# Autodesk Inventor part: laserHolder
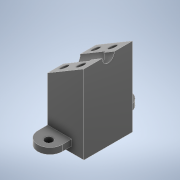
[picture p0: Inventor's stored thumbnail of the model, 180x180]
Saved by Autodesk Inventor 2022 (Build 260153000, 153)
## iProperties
Created: 2022-11
Part Number: laserHolder
Material: Acetal Resin, Black
Document SubType Name: Modeling
Designer: Wojtus
Density: 1.425 g/cm^3
Appearance: Smooth - Black
Author: Wojtus
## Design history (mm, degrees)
sketch "Sketch1"
  geometry: L1 (7.5, -10)-(7.5, 10); L2 (7.5, 10)-(-7.5, 10); L3 (-7.5, 10)-(-7.5, -10); L4 (-7.5, -10)-(7.5, 10); L5 (7.5, -10)-(-7.5, 10); L6 (7.5, -10)-(-7.5, -10); L7 (7.5, 10)-(-2.5, 10); L8 (-2.5, 10)-(-2.5, 14); L9 (7.5, 14)-(7.5, 10); L10 (-7.5, -10)-(-5.5, -10); L11 (0.5, -10)-(7.5, -10); L12 (0, 0)-(-3.6, 0); L13 (7.5, -14)-(7.5, -10); L14 (-2.5, -10)-(-2.5, -14); A1 r 5 centre (2.5, 14) between (7.5, 14) and (-2.5, 14); A2 r 5 centre (2.5, -14) between (-2.5, -14) and (7.5, -14); 8 further points
  constraints: 28 end point, 5 horizontal, 4 parallel, 4 point on circle, 4 symmetric about line, 3 perpendicular, 3 point on line, 2 centre point, 2 midpoint, 1 other
  dimensions: "d0" = 15 distance of L2.end L1.end; "d1" = 20 distance of L1.end L1.start; "d21" = 5 distance between parallel lines of L3 L8; "d22" = 4 distance from line of L2 L9.start; "d23" = 10 distance between parallel lines of L8 L9; "d24" = 4 distance from line of L2 A1.centre; "d25" = 5 radius of A1
extrude "Extrusion1" new body sketch "Sketch1" stored distance "d4" = 5; taper "d5" = 0 deg
extrude "Extrusion2" cut sketch "Sketch1" extent not by distance; stored distance "d6" = 0; taper "d7" = 0 deg
sketch "Sketch2"
  geometry: L1 (2.5, -10)-(-7.5, -10) reference; L2 (0, 0)-(3.608, 0); L3 (-7.5, 14)-(-7.5, -14) reference; C1 r 1.6 at (-2, -15); C2 r 1.6 at (-2, 15); 2 further points
  constraints: 2 centre point, 2 end point, 1 horizontal, 1 symmetric about line, 1 other
  dimensions: "d9" = 3.2 diameter of C1; "d10" = 5 distance from line of L1 C1.centre; "d51" = 5.5 distance from line of C1.centre L3
extrude "Extrusion3" cut sketch "Sketch2" distance "d12" = 10; taper "d13" = 0 deg
extrude "Extrusion4" join sketch "Sketch1" distance "d26" = 30; taper "d27" = 0 deg
sketch "Sketch4"
  geometry: L1 (0, 5)-(0, 32.5) reference; L2 (15, 32.5)-(0, 32.5) reference; L3 (0, 32.5)-(15, 32.5); L4 (15, 32.5)-(0, 23.59); L5 (0, 23.59)-(0, 32.5); 2 further points
  constraints: 6 end point, 1 horizontal, 1 perpendicular
  dimensions: "d52" = 30.7103 deg angle of L2 L4
extrude "Extrusion5" cut sketch "Sketch4" extent not by distance; stored distance "d29" = 0; taper "d30" = 0 deg
sketch "Sketch9"
  geometry: L1 (-6.94, 13.5)-(12.447, 13.5) reference; L2 (12.447, 12.5)-(17.447, 12.5) reference; L3 (17.447, 10)-(12.447, 10) reference; L4 (12.447, 10)-(12.447, 12.5) reference; L5 (12.447, 10)-(-6.94, 10) reference; L6 (-6.94, 0)-(-6.94, 20) reference; L7 (12.447, 13.5)-(12.447, 12.5); L8 (17.447, 12.5)-(17.447, 10); L9 (17.447, 0)-(17.447, 20) reference; 1 further point
  constraints: 4 end point, 1 collinear, 1 vertical
revolve "Revolution3" sketch "Sketch9" stored, may be unused: angle "d53" = 360 deg
sketch "Sketch10"
  geometry: L1 (0, -5)-(-5, -5) reference; L2 (-17.447, -12.5)-(-17.447, -6) reference; C1 r 1.6 at (-13.447, -9); C2 r 1.6 at (-5.447, -9); C3 r 1.6 at (-13.447, 4); C4 r 1.6 at (-5.447, 4); 1 further point
  constraints: 4 centre point, 1 horizontal, 1 vertical, 6 other
  dimensions: "d54" = 3.2 diameter of C1; "d55" = 4 distance from line of L1 C1.centre; "d56" = 4 distance from line of L2 C1.centre; "d59" = 8 distance of C1.centre C2.centre; "d62" = 13 distance of C1.centre C3.centre
extrude "Extrusion7" cut sketch "Sketch10" distance "d65" = 4; taper "d66" = 0 deg
body "Solid1"
